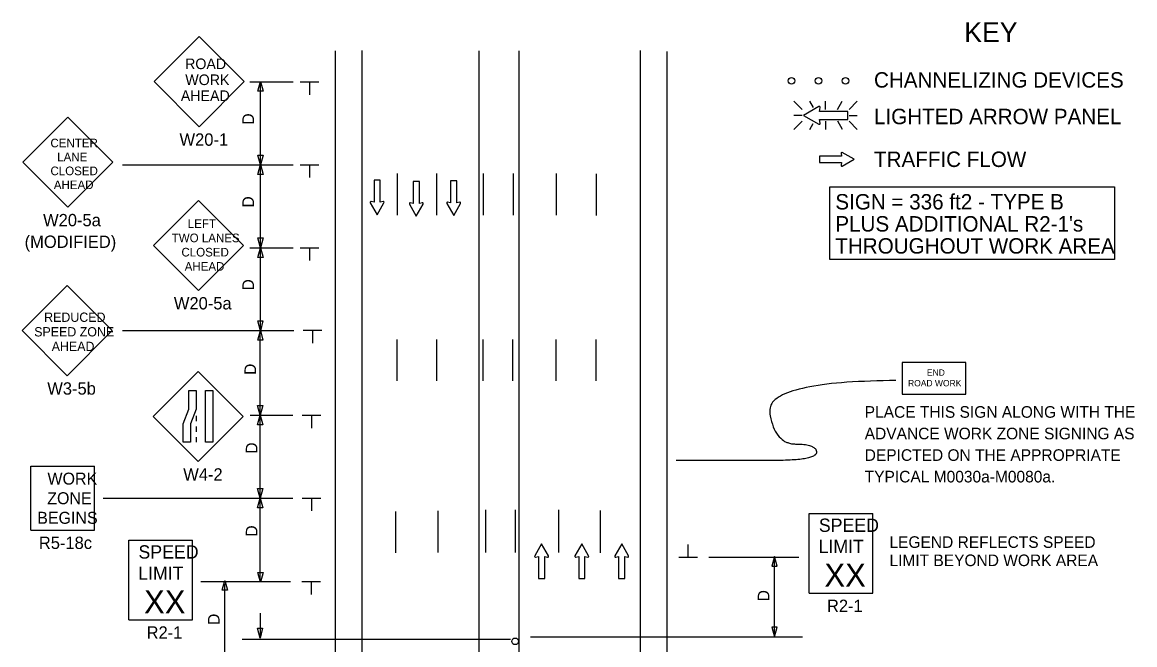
# Model space of a CAD drawing. Extents: x 20837 to 23689, y 414 to 2167.
# Drawn here: x 20925 to 21596, y 1279 to 1654 of the extents above; entities that cross this region are included whole.
import ezdxf

# ---------------------------------------------------------------- set-up
doc = ezdxf.new("R2010")
doc.units = 0
for name, color, linetype in [('ALI_LEGAL_EX', 7, 'Continuous'), ('MT_SCRATCH_LEVEL_E', 7, 'Continuous'), ('PAVT_EDGE_EX', 7, 'Continuous'), ('TRAFFIC_SIGNS_PR', 7, 'Continuous'), ('TYPICAL_EX', 7, 'Continuous'), ('TYPICAL_TEXT_DIMEN_EX', 7, 'Continuous'), ('TYPICAL_TEXT_DIMEN_PR', 7, 'Continuous')]:
    doc.layers.add(name, color=color, linetype=linetype)

msp = doc.modelspace()

# ---------------------------------------------------------------- linework, layer by layer
at = {"layer": 'ALI_LEGAL_EX'}
for points in [[(21150.97, 1538.09), (21150.97, 1563.09)], [(21174.75, 1538.09), (21174.75, 1563.09)], [(21202.97, 1538.09), (21202.97, 1563.09)], [(21220.87, 1538.09), (21220.87, 1563.09)], [(21246.97, 1538.09), (21246.97, 1563.09)], [(21270.97, 1537.88), (21270.97, 1562.88)], [(21150.75, 1438.1), (21150.75, 1463.1)], [(21174.75, 1438.1), (21174.75, 1463.1)], [(21202.75, 1438.1), (21202.75, 1463.1)], [(21220.65, 1438.1), (21220.65, 1463.1)], [(21246.75, 1438.1), (21246.75, 1463.1)], [(21270.75, 1438.1), (21270.75, 1463.1)], [(21149.95, 1334.41), (21149.95, 1359.42)], [(21175.6, 1334.71), (21175.6, 1359.72)], [(21204.24, 1334.7), (21204.24, 1360.39)], [(21222.15, 1334.7), (21222.15, 1360.39)], [(21248.24, 1334.7), (21248.24, 1360.39)], [(21273.43, 1334.46), (21273.43, 1359.98)]]:
    msp.add_lwpolyline(points, dxfattribs=at)
at = {"layer": 'MT_SCRATCH_LEVEL_E'}
for p, q in [((21418.89, 1573.64), (21405.63, 1573.64)), ((21405.63, 1573.64), (21405.63, 1569.9)), ((21418.89, 1573.64), (21405.63, 1573.64)), ((21405.63, 1573.64), (21405.63, 1569.9)), ((21418.57, 1575.42), (21418.89, 1573.64)), ((21418.57, 1575.42), (21418.89, 1573.64)), ((21426.5, 1571.79), (21419.26, 1575.9)), ((21426.5, 1571.79), (21419.26, 1575.9)), ((21419.26, 1567.64), (21426.5, 1571.79)), ((21419.26, 1567.64), (21426.5, 1571.79)), ((21405.63, 1569.9), (21418.89, 1569.9)), ((21405.63, 1569.9), (21418.89, 1569.9)), ((21418.89, 1569.9), (21418.57, 1568.12)), ((21418.89, 1569.9), (21418.57, 1568.12)), ((21140.57, 1559.19), (21136.82, 1559.19)), ((21136.82, 1559.19), (21136.82, 1545.93)), ((21140.57, 1559.19), (21136.82, 1559.19)), ((21136.82, 1559.19), (21136.82, 1545.93)), ((21140.57, 1545.93), (21140.57, 1559.19)), ((21140.57, 1545.93), (21140.57, 1559.19)), ((21164.2, 1558.36), (21160.46, 1558.36)), ((21160.46, 1558.36), (21160.46, 1545.11)), ((21164.2, 1558.36), (21160.46, 1558.36)), ((21160.46, 1558.36), (21160.46, 1545.11)), ((21164.2, 1545.11), (21164.2, 1558.36)), ((21164.2, 1545.11), (21164.2, 1558.36)), ((21186.73, 1558.78), (21182.99, 1558.78)), ((21182.99, 1558.78), (21182.99, 1545.52)), ((21186.73, 1558.78), (21182.99, 1558.78)), ((21182.99, 1558.78), (21182.99, 1545.52)), ((21186.73, 1545.52), (21186.73, 1558.78)), ((21186.73, 1545.52), (21186.73, 1558.78)), ((21134.57, 1545.56), (21138.71, 1538.32)), ((21134.57, 1545.56), (21138.71, 1538.32)), ((21136.82, 1545.93), (21135.05, 1546.25)), ((21136.82, 1545.93), (21135.05, 1546.25)), ((21138.71, 1538.32), (21142.83, 1545.56)), ((21138.71, 1538.32), (21142.83, 1545.56)), ((21142.34, 1546.25), (21140.57, 1545.93)), ((21142.34, 1546.25), (21140.57, 1545.93)), ((21158.2, 1544.74), (21162.35, 1537.5)), ((21158.2, 1544.74), (21162.35, 1537.5)), ((21160.46, 1545.11), (21158.68, 1545.42)), ((21160.46, 1545.11), (21158.68, 1545.42)), ((21162.35, 1537.5), (21166.46, 1544.74)), ((21162.35, 1537.5), (21166.46, 1544.74)), ((21165.98, 1545.42), (21164.2, 1545.11)), ((21165.98, 1545.42), (21164.2, 1545.11)), ((21180.73, 1545.15), (21184.88, 1537.91)), ((21180.73, 1545.15), (21184.88, 1537.91)), ((21182.99, 1545.52), (21181.21, 1545.83)), ((21182.99, 1545.52), (21181.21, 1545.83)), ((21184.88, 1537.91), (21188.99, 1545.15)), ((21184.88, 1537.91), (21188.99, 1545.15)), ((21188.51, 1545.83), (21186.73, 1545.52)), ((21188.51, 1545.83), (21186.73, 1545.52)), ((21237.9, 1339.82), (21233.79, 1332.58)), ((21237.9, 1339.82), (21233.79, 1332.58)), ((21242.05, 1332.58), (21237.9, 1339.82)), ((21242.05, 1332.58), (21237.9, 1339.82)), ((21262.17, 1339.82), (21258.06, 1332.58)), ((21262.17, 1339.82), (21258.06, 1332.58)), ((21266.31, 1332.58), (21262.17, 1339.82)), ((21266.31, 1332.58), (21262.17, 1339.82)), ((21286.24, 1339.82), (21282.13, 1332.58)), ((21286.24, 1339.82), (21282.13, 1332.58)), ((21290.39, 1332.58), (21286.24, 1339.82)), ((21290.39, 1332.58), (21286.24, 1339.82)), ((21234.27, 1331.89), (21236.05, 1332.21)), ((21234.27, 1331.89), (21236.05, 1332.21)), ((21236.05, 1332.21), (21236.05, 1318.95)), ((21236.05, 1332.21), (21236.05, 1318.95)), ((21239.79, 1318.95), (21239.79, 1332.21)), ((21239.79, 1332.21), (21241.57, 1331.89)), ((21239.79, 1318.95), (21239.79, 1332.21)), ((21239.79, 1332.21), (21241.57, 1331.89)), ((21258.54, 1331.89), (21260.32, 1332.21)), ((21258.54, 1331.89), (21260.32, 1332.21)), ((21260.32, 1332.21), (21260.32, 1318.95)), ((21260.32, 1332.21), (21260.32, 1318.95)), ((21264.06, 1318.95), (21264.06, 1332.21)), ((21264.06, 1332.21), (21265.84, 1331.89)), ((21264.06, 1318.95), (21264.06, 1332.21)), ((21264.06, 1332.21), (21265.84, 1331.89)), ((21282.61, 1331.89), (21284.39, 1332.21)), ((21282.61, 1331.89), (21284.39, 1332.21)), ((21284.39, 1332.21), (21284.39, 1318.95)), ((21284.39, 1332.21), (21284.39, 1318.95)), ((21288.13, 1318.95), (21288.13, 1332.21)), ((21288.13, 1332.21), (21289.91, 1331.89)), ((21288.13, 1318.95), (21288.13, 1332.21)), ((21288.13, 1332.21), (21289.91, 1331.89)), ((21236.05, 1318.95), (21239.79, 1318.95)), ((21236.05, 1318.95), (21239.79, 1318.95)), ((21260.32, 1318.95), (21264.06, 1318.95)), ((21260.32, 1318.95), (21264.06, 1318.95)), ((21284.39, 1318.95), (21288.13, 1318.95)), ((21284.39, 1318.95), (21288.13, 1318.95))]:
    msp.add_line(p, q, dxfattribs=at)
for centre, start, end in [((21419.03, 1575.49), 60.42484, 189.96381), ((21419.03, 1575.49), 60.42484, 189.96381), ((21419.03, 1568.05), 170.03619, 299.77312), ((21419.03, 1568.05), 170.03619, 299.77312), ((21134.98, 1545.79), 80.03619, 209.77312), ((21134.98, 1545.79), 80.03619, 209.77312), ((21142.42, 1545.79), 330.42484, 99.96381), ((21142.42, 1545.79), 330.42484, 99.96381), ((21158.61, 1544.96), 80.03619, 209.77312), ((21158.61, 1544.96), 80.03619, 209.77312), ((21166.05, 1544.96), 330.42484, 99.96381), ((21166.05, 1544.96), 330.42484, 99.96381), ((21181.14, 1545.37), 80.03619, 209.77312), ((21181.14, 1545.37), 80.03619, 209.77312), ((21188.58, 1545.38), 330.42484, 99.96381), ((21188.58, 1545.38), 330.42484, 99.96381), ((21234.2, 1332.35), 150.42484, 279.96381), ((21234.2, 1332.35), 150.42484, 279.96381), ((21241.64, 1332.35), 260.03619, 29.77312), ((21241.64, 1332.35), 260.03619, 29.77312), ((21258.46, 1332.35), 150.42484, 279.96381), ((21258.46, 1332.35), 150.42484, 279.96381), ((21265.9, 1332.35), 260.03619, 29.77312), ((21265.9, 1332.35), 260.03619, 29.77312), ((21282.54, 1332.35), 150.42484, 279.96381), ((21282.54, 1332.35), 150.42484, 279.96381), ((21289.98, 1332.35), 260.03619, 29.77312), ((21289.98, 1332.35), 260.03619, 29.77312)]:
    msp.add_arc(centre, 0.463, start, end, dxfattribs=at)
at = {"layer": 'PAVT_EDGE_EX'}
for p, q in [((21129.4, 1637.35), (21129.4, 831.94)), ((21200.14, 1637.05), (21200.14, 1162.94)), ((21224.14, 1637.05), (21224.14, 1153.29)), ((21297.4, 1637.35), (21297.4, 831.94)), ((21313.4, 1636.75), (21313.4, 831.94))]:
    msp.add_line(p, q, dxfattribs=at)
at = {"layer": 'TRAFFIC_SIGNS_PR'}
for p, q in [((21031.32, 1645.74), (21004.13, 1618.55)), ((21058.51, 1618.55), (21031.32, 1645.74)), ((21004.13, 1618.55), (21031.32, 1591.37)), ((21031.32, 1591.37), (21058.51, 1618.55)), ((21390.18, 1606.73), (21395.11, 1601.8)), ((21401.94, 1602.91), (21399.74, 1606.73)), ((21409.26, 1601.8), (21409.26, 1606.73)), ((21416.5, 1601.8), (21419.35, 1606.73)), ((21423.41, 1601.8), (21428.35, 1606.73)), ((21395.11, 1598.24), (21390.18, 1598.24)), ((21423.41, 1598.24), (21428.35, 1598.24)), ((20952.05, 1597.1), (20924.89, 1569.94)), ((20979.2, 1569.94), (20952.05, 1597.1)), ((21390.18, 1589.75), (21395.11, 1594.68)), ((21399.69, 1589.75), (21401.8, 1593.41)), ((21409.26, 1594.68), (21409.26, 1589.75)), ((21419.39, 1589.75), (21416.54, 1594.68)), ((21423.41, 1594.68), (21428.35, 1589.75)), ((20924.89, 1569.94), (20952.05, 1542.79)), ((20952.05, 1542.79), (20979.2, 1569.94)), ((21030.94, 1546.95), (21003.79, 1519.8)), ((21058.09, 1519.8), (21030.94, 1546.95)), ((21003.79, 1519.8), (21030.94, 1492.65)), ((21030.94, 1492.65), (21058.09, 1519.8)), ((20951.76, 1495.58), (20924.6, 1468.42)), ((20978.91, 1468.42), (20951.76, 1495.58)), ((20924.6, 1468.42), (20951.76, 1441.27)), ((20951.76, 1441.27), (20978.91, 1468.42)), ((21030.78, 1443.75), (21003.62, 1416.6)), ((21057.93, 1416.6), (21030.78, 1443.75)), ((21003.62, 1416.6), (21030.78, 1389.44)), ((21029.53, 1417.09), (21029.53, 1413.89)), ((21030.78, 1389.44), (21057.93, 1416.6)), ((21029.53, 1410.69), (21029.53, 1407.49)), ((21029.53, 1404.29), (21029.53, 1401.09)), ((20929.81, 1348.22), (20929.81, 1386.62)), ((20929.81, 1386.62), (20968.21, 1386.62)), ((20968.21, 1348.22), (20968.21, 1386.62)), ((21399.41, 1358.23), (21437.81, 1358.23)), ((21399.41, 1310.23), (21399.41, 1358.23)), ((21437.81, 1310.23), (21437.81, 1358.23)), ((20929.81, 1348.22), (20968.21, 1348.22)), ((20988.96, 1342.14), (21027.36, 1342.14)), ((20988.96, 1294.14), (20988.96, 1342.14)), ((21027.36, 1294.14), (21027.36, 1342.14)), ((21399.41, 1310.23), (21437.81, 1310.23)), ((20988.96, 1294.14), (21027.36, 1294.14))]:
    msp.add_line(p, q, dxfattribs=at)
for points in [[(21405.19, 1603.52), (21395.9, 1598.24), (21405.19, 1592.92)], [(21406.07, 1593.55), (21405.66, 1595.81), (21422.68, 1595.81), (21422.68, 1600.62), (21405.66, 1600.62), (21406.07, 1602.9)]]:
    msp.add_lwpolyline(points, dxfattribs=at)
for points in [[(21455.39, 1430.1), (21493.79, 1430.1), (21493.79, 1449.3), (21455.39, 1449.3)], [(21029.53, 1432.33), (21029.53, 1421.15), (21026.18, 1412.27), (21026.18, 1401.09), (21021.69, 1401.09), (21021.69, 1412.27), (21025.03, 1421.15), (21025.03, 1432.33)], [(21039.66, 1432.33), (21039.66, 1401.09), (21035.17, 1401.09), (21035.17, 1432.33)]]:
    msp.add_lwpolyline(points, close=True, dxfattribs=at)
for centre in [(21388.69, 1619.08), (21404.99, 1619.08), (21421.29, 1619.08), (21222.02, 1281.09), (21222.02, 1281.09)]:
    msp.add_circle(centre, 2, dxfattribs=at)
for centre, radius, start, end in [((21405.48, 1602.99), 0.598, 350.73078, 118.89165), ((21405.48, 1593.44), 0.597, 241.48329, 9.95933)]:
    msp.add_arc(centre, radius, start, end, dxfattribs=at)
at = {"layer": 'TYPICAL_EX'}
msp.add_line((21113.4, 1637.05), (21113.4, 832.24), dxfattribs=at)
at = {"layer": 'TYPICAL_TEXT_DIMEN_EX'}
msp.add_lwpolyline([(21411.78, 1555.18), (21583.51, 1555.18), (21583.51, 1511.22), (21411.78, 1511.22)], close=True, dxfattribs=at)
at = {"layer": 'TYPICAL_TEXT_DIMEN_PR'}
for p, q in [((21061.97, 1618.45), (21087.97, 1618.45)), ((21066.82, 1612.74), (21068.39, 1618.6)), ((21068.31, 1568.6), (21068.31, 1618.6)), ((21068.39, 1618.6), (21069.96, 1612.74)), ((21092.22, 1618.45), (21103.47, 1618.45)), ((21097.84, 1618.45), (21097.84, 1610.66)), ((21068.39, 1612.74), (21066.82, 1612.74)), ((21069.96, 1612.74), (21068.39, 1612.74)), ((21068.31, 1568.38), (21066.74, 1574.24)), ((21066.74, 1574.24), (21068.31, 1574.24)), ((21068.31, 1574.24), (21069.88, 1574.24)), ((21069.88, 1574.24), (21068.31, 1568.38)), ((20985.01, 1568.45), (21087.97, 1568.45)), ((21066.74, 1562.66), (21068.31, 1568.52)), ((21068.31, 1518.52), (21068.31, 1568.52)), ((21068.31, 1568.52), (21069.88, 1562.66)), ((21092.22, 1568.45), (21103.47, 1568.45)), ((21097.84, 1568.45), (21097.84, 1560.66)), ((21068.31, 1562.66), (21066.74, 1562.66)), ((21069.88, 1562.66), (21068.31, 1562.66)), ((21068.31, 1518.45), (21066.74, 1524.31)), ((21066.74, 1524.31), (21068.31, 1524.31)), ((21068.31, 1524.31), (21069.88, 1524.31)), ((21069.88, 1524.31), (21068.31, 1518.45)), ((21061.97, 1518.45), (21087.97, 1518.45)), ((21066.82, 1512.59), (21068.39, 1518.45)), ((21068.27, 1468.49), (21068.27, 1518.49)), ((21068.39, 1518.45), (21069.96, 1512.59)), ((21092.22, 1518.45), (21103.47, 1518.45)), ((21097.84, 1518.45), (21097.84, 1510.66)), ((21068.39, 1512.59), (21066.82, 1512.59)), ((21069.96, 1512.59), (21068.39, 1512.59)), ((21068.27, 1468.39), (21066.7, 1474.26)), ((21066.7, 1474.26), (21068.27, 1474.26)), ((21068.27, 1474.26), (21069.84, 1474.26)), ((21069.84, 1474.26), (21068.27, 1468.39)), ((20985.01, 1468.42), (21088.42, 1468.42)), ((21066.7, 1462.6), (21068.27, 1468.46)), ((21068.23, 1418.42), (21068.23, 1468.42)), ((21068.27, 1468.46), (21069.84, 1462.6)), ((21094.12, 1468.72), (21105.37, 1468.72)), ((21099.74, 1468.72), (21099.74, 1460.94)), ((21068.27, 1462.6), (21066.7, 1462.6)), ((21069.84, 1462.6), (21068.27, 1462.6)), ((21068.19, 1417.38), (21066.62, 1423.24)), ((21066.62, 1423.24), (21068.19, 1423.24)), ((21068.19, 1423.24), (21069.76, 1423.24)), ((21069.76, 1423.24), (21068.19, 1417.38)), ((21062.17, 1417.46), (21087.78, 1417.46)), ((21066.62, 1411.57), (21068.19, 1417.43)), ((21068.19, 1417.43), (21069.76, 1411.57)), ((21068.23, 1368.42), (21068.23, 1418.42)), ((21093.48, 1417.51), (21104.73, 1417.51)), ((21099.11, 1417.51), (21099.11, 1409.72)), ((21068.19, 1411.57), (21066.62, 1411.57)), ((21069.76, 1411.57), (21068.19, 1411.57)), ((21068.19, 1367.38), (21066.62, 1373.24)), ((21066.62, 1373.24), (21068.19, 1373.24)), ((21068.19, 1373.24), (21069.76, 1373.24)), ((21069.76, 1373.24), (21068.19, 1367.38)), ((20973.52, 1367.46), (21087.78, 1367.46)), ((21066.62, 1361.57), (21068.19, 1367.43)), ((21068.19, 1367.43), (21069.76, 1361.57)), ((21068.23, 1317.21), (21068.23, 1367.21)), ((21093.48, 1367.51), (21104.73, 1367.51)), ((21099.11, 1367.51), (21099.11, 1359.72)), ((21068.19, 1361.57), (21066.62, 1361.57)), ((21069.76, 1361.57), (21068.19, 1361.57)), ((21326.4, 1331.64), (21326.4, 1339.42)), ((21332.02, 1331.64), (21320.77, 1331.64)), ((21393.06, 1331.64), (21338.79, 1331.64)), ((21378.48, 1332.21), (21376.91, 1326.35)), ((21380.05, 1326.35), (21378.48, 1332.21)), ((21378.49, 1283.86), (21378.49, 1330.2)), ((21068.35, 1316.76), (21066.78, 1322.62)), ((21066.78, 1322.62), (21068.35, 1322.62)), ((21068.35, 1322.62), (21069.92, 1322.62)), ((21069.92, 1322.62), (21068.35, 1316.76)), ((21376.91, 1326.35), (21378.48, 1326.35)), ((21378.48, 1326.35), (21380.05, 1326.35)), ((21032.25, 1317.17), (21086.52, 1317.17)), ((21045.26, 1311.88), (21046.83, 1317.75)), ((21046.82, 1269.4), (21046.82, 1315.73)), ((21046.83, 1317.75), (21048.4, 1311.88)), ((21093.29, 1317.17), (21104.54, 1317.17)), ((21098.91, 1317.17), (21098.91, 1309.39)), ((21046.83, 1311.88), (21045.26, 1311.88)), ((21048.4, 1311.88), (21046.83, 1311.88)), ((21068.04, 1298.02), (21068.04, 1283.1)), ((21068.04, 1283.1), (21066.47, 1288.96)), ((21066.47, 1288.96), (21068.04, 1288.96)), ((21068.04, 1288.96), (21069.61, 1288.96)), ((21069.61, 1288.96), (21068.04, 1283.1)), ((21378.48, 1289.61), (21376.91, 1289.61)), ((21376.91, 1289.61), (21378.48, 1283.74)), ((21378.48, 1283.74), (21380.05, 1289.61)), ((21380.05, 1289.61), (21378.48, 1289.61)), ((21057.29, 1282.33), (21219.19, 1282.33)), ((21395.33, 1283.55), (21231.21, 1283.55))]:
    msp.add_line(p, q, dxfattribs=at)
msp.add_open_spline([(21451.67, 1438.45), (21372.45, 1437.49), (21378.58, 1400.08), (21403.75, 1400.08), (21403.75, 1390.17), (21354.11, 1390.17), (21319.04, 1390.17)], degree=2, dxfattribs=at)

# ---------------------------------------------------------------- texts
at = {"layer": 'TRAFFIC_SIGNS_PR'}
for s, height, p in [('ROAD', 6.408, (21022.85, 1626.1)), ('WORK', 6.408, (21022.96, 1616.48)), ('AHEAD', 6.408, (21020.27, 1606.87)), ('CENTER', 5.2, (20941.62, 1578.95)), ('W20-1', 7.449, (21019.47, 1579.91)), ('LANE', 5.2, (20945.7, 1570.55)), ('CLOSED', 5.2, (20941.63, 1562.15)), ('AHEAD', 5.2, (20943.65, 1553.75)), ('W20-5a', 7.44, (20937.18, 1531.35)), ('LEFT', 5.2, (21024.48, 1530.34)), ('(MODIFIED)', 7.44, (20926.04, 1518.31)), ('TWO LANES', 5.2, (21014.8, 1521.74)), ('CLOSED', 5.2, (21020.65, 1513.14)), ('AHEAD', 5.2, (21022.6, 1504.54)), ('W20-5a', 7.44, (21016.08, 1481.21)), ('REDUCED', 5.6, (20937.81, 1473.73)), ('SPEED ZONE', 5.6, (20931.81, 1464.93)), ('AHEAD', 5.6, (20942.37, 1456.13)), ('END', 3.831, (21470.4, 1441.23)), ('W3-5b', 7.44, (20939.71, 1429.83)), ('ROAD WORK', 3.831, (21459, 1434.84)), ('PLACE THIS SIGN ALONG WITH THE', 7, (21432.85, 1415.9)), ('ADVANCE WORK ZONE SIGNING AS', 7, (21432.85, 1402.9)), ('DEPICTED ON THE APPROPRIATE', 7, (21432.85, 1389.9)), ('WORK', 7.217, (20939.81, 1375.59)), ('W4-2', 7.44, (21021.73, 1378)), ('TYPICAL M0030a-M0080a.', 7, (21432.85, 1376.9)), ('ZONE', 7.217, (20939.69, 1363.78)), ('BEGINS', 7.217, (20933.62, 1351.97)), ('SPEED', 8, (21405.18, 1347.1)), ('R5-18c', 7.44, (20934.62, 1336.78)), ('LEGEND REFLECTS SPEED', 7, (21447.79, 1337.44)), ('SPEED', 8, (20994.72, 1331)), ('LIMIT', 8, (21405.02, 1334.3)), ('LIMIT BEYOND WORK AREA', 7, (21447.79, 1326.44)), ('LIMIT', 8, (20994.56, 1318.2)), ('XX', 14.031, (21408.52, 1313.99)), ('XX', 14.031, (20998.07, 1297.9)), ('R2-1', 7.44, (21410.09, 1298.79)), ('R2-1', 7.44, (20999.63, 1282.7))]:
    msp.add_text(s, height=height, dxfattribs=at).set_placement(p)
at = {"layer": 'TYPICAL_TEXT_DIMEN_EX'}
for s, height, p in [('KEY', 12, (21492.94, 1642.36)), ('CHANNELIZING DEVICES', 9.3, (21438.46, 1614.95)), ('LIGHTED ARROW PANEL', 9.3, (21438.46, 1592.9)), ('TRAFFIC FLOW', 9.3, (21438.46, 1567.1)), ('SIGN = 336 ft2 - TYPE B', 9.3, (21415.12, 1541.47)), ("PLUS ADDITIONAL R2-1's", 9.3, (21415.12, 1528.17)), ('THROUGHOUT WORK AREA', 9.3, (21415.12, 1514.87))]:
    msp.add_text(s, height=height, dxfattribs=at).set_placement(p)
at = {"layer": 'TYPICAL_TEXT_DIMEN_PR'}
for p in [(21064.41, 1592.67), (21064.41, 1542.67), (21064.41, 1492.67), (21065.67, 1441.75), (21066.47, 1394.25), (21066.47, 1344.25), (21375.33, 1305.24), (21043.66, 1291.01)]:
    msp.add_text('D', height=7, rotation=90, dxfattribs=at).set_placement(p)

doc.saveas('drawing.dxf')
